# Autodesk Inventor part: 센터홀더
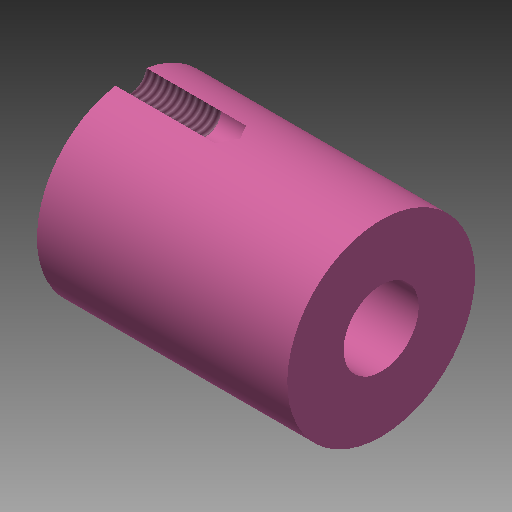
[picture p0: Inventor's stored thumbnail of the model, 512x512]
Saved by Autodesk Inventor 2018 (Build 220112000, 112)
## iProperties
Created: 2019-10
Part Number: 센터홀더
Material: 강철, 연강
Document SubType Name: Modeling
Designer: mduedu
Density: 1 g/cm^3
Appearance: 분홍색
Author: mduedu
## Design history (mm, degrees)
sketch "스케치1"
  geometry: L1 (0, 0)-(20, 0); L2 (12, -3)-(20, -3); L3 (20, -3)-(20, -7.5); L4 (20, -7.5)-(0, -7.5); L5 (0, -7.5)-(0, -4.127); L6 (0, -4.127)-(12, -3.751); L7 (12, -3.751)-(12, -3)
  constraints: 14 end point, 2 horizontal, 2 parallel, 2 perpendicular, 2 vertical alignment
  dimensions: "d0" = 20 distance of L1.start L1.end; "d1" = 6 diameter of L2 L1; "d2" = 12 distance between parallel lines of L5 L7; "d3" = 7.502 diameter of L6.end L1; "d4" = 8.254 diameter of L5.end L1; "d5" = 15 diameter of L4 L1
revolve "회전1" sketch "스케치1" stored, may be unused: angle "d6" = 90 deg
sketch "스케치2"
  geometry: 3 further points
  constraints: 2 vertical alignment, 1 other
hole "구멍1" sketch "스케치2" at (0, 7.5) diameter "d7" = 2.459; stored, may be unused: countersink angle "d11" = 90 deg, drill point angle "d13" = 118 deg; dims "d8" = 6, "d9" = 4, "d10" = 2, "d12" = 8
node "솔리드1"
